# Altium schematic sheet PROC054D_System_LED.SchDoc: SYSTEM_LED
size 558 x 431 mm; Date: Not shown in title block; ApprovedBy: Not shown in title block; CheckedBy: Not shown in title block; Author: Not shown in title block; CompanyName: Not shown in title block; DrawnBy: a0271760; Engineer: Not shown in title block; Organization: Not shown in title block; Address1: Not shown in title block; Address2: Not shown in title block; Address3: Not shown in title block; Address4: Not shown in title block; DocumentNumber: 17; Revision: Use project pAWRameter SCH_Rev; SheetNumber: 17; SheetTotal: 19; PageSetup: Record=PageOptions¦CenterHorizontal=True¦CenterVertical=True¦PrintScale=1.00¦XCorrection=1.00¦YCorrection=1.00¦PrintKind=0¦BorderSize=5000000¦LeftOffset=0¦BottomOffset=0¦Orientation=2¦PaperLength=1000¦PaperWidth=1000¦Scale=100¦PaperSource=15¦PrintQuality=600¦MediaType=1¦DitherType=10¦PaperKind=Letter¦PrintScaleMode=1
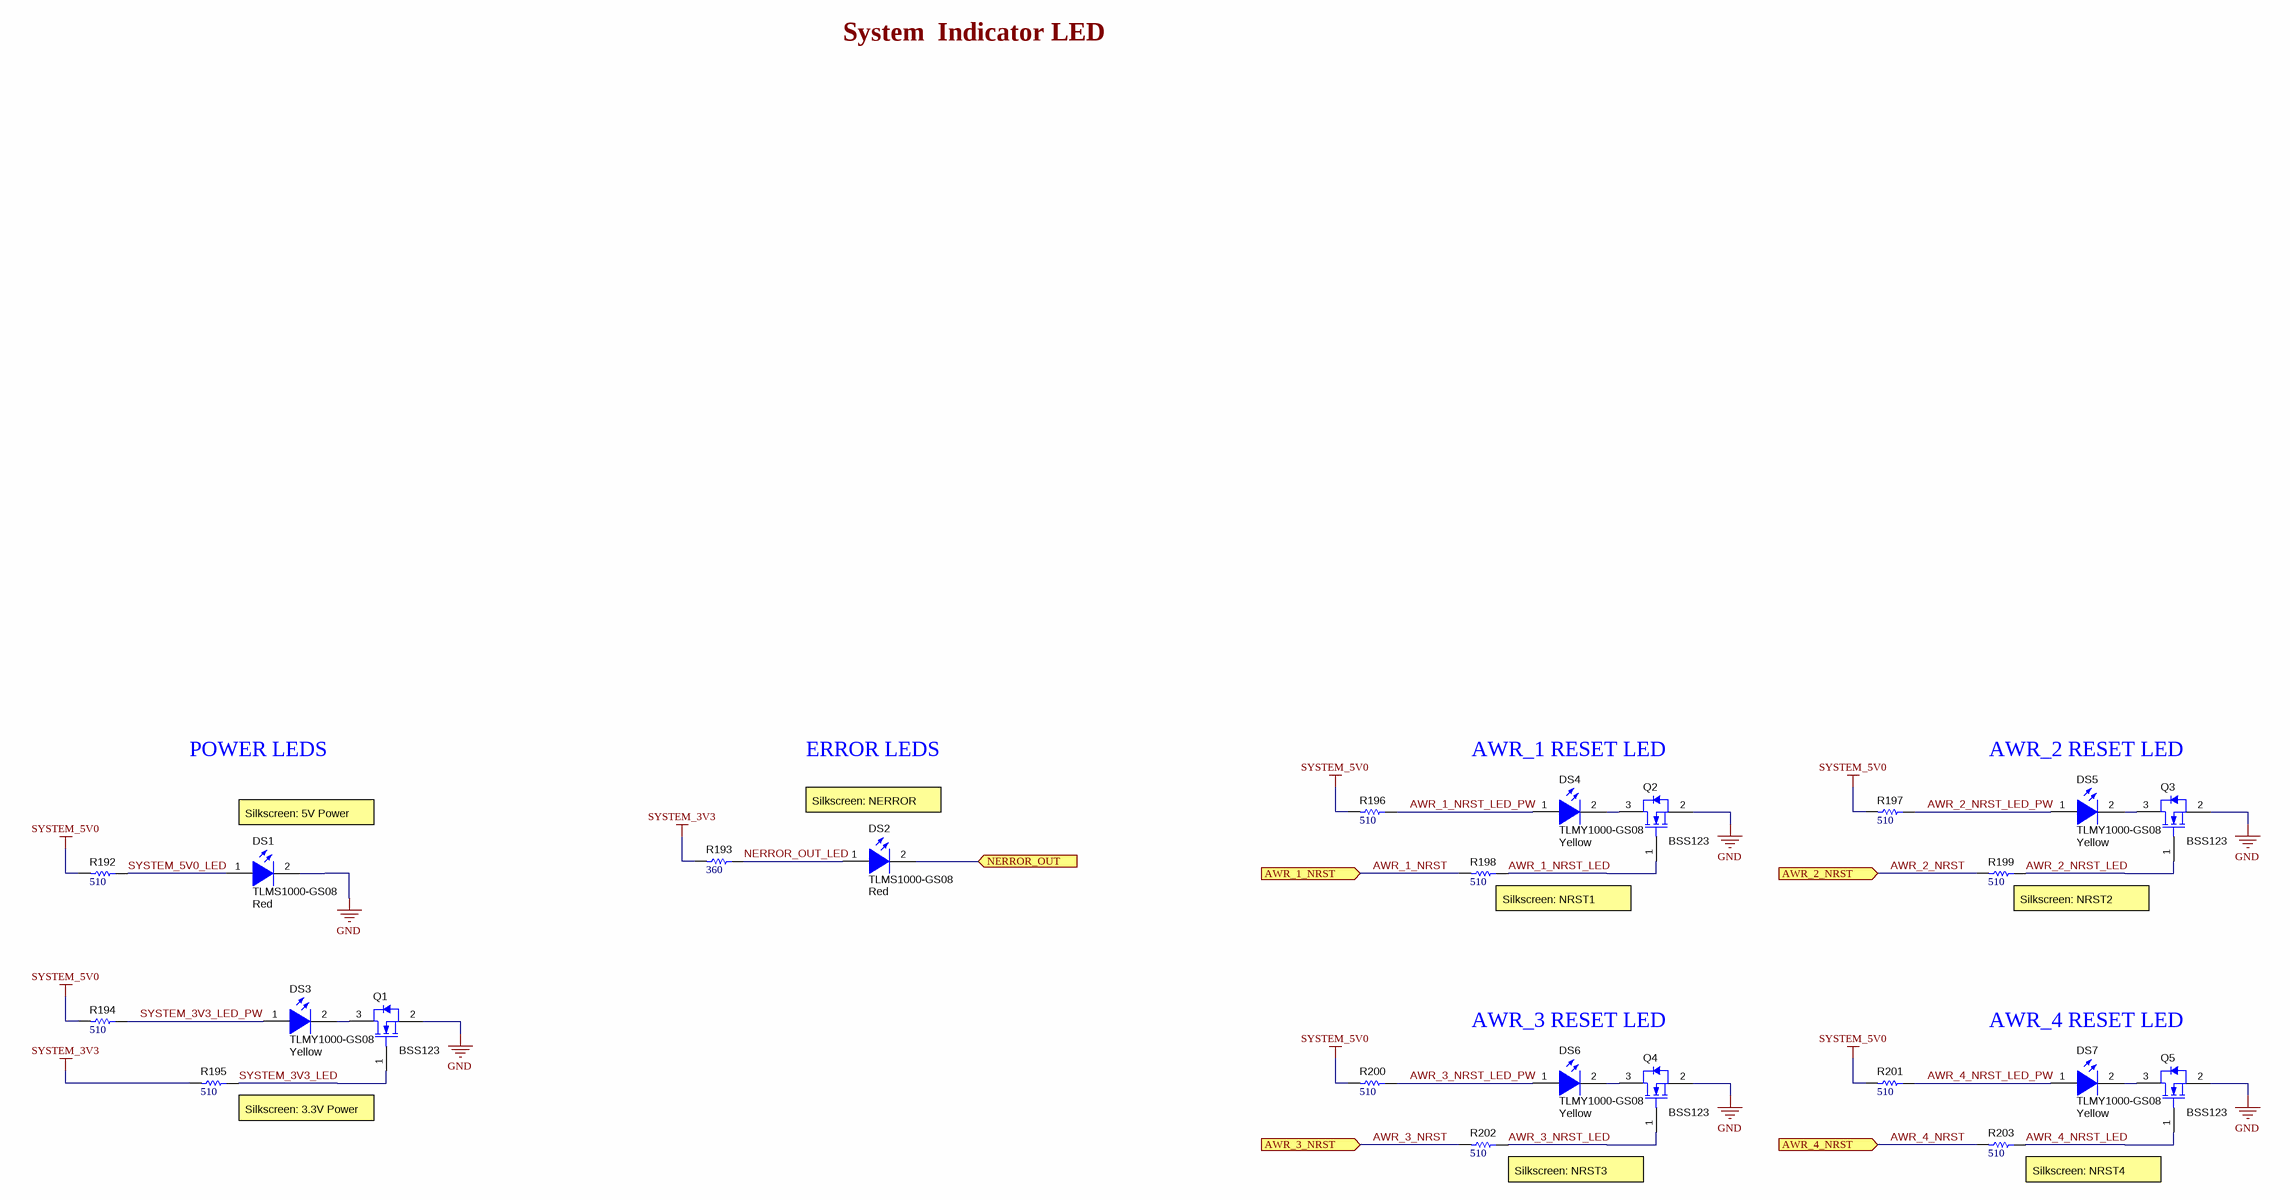
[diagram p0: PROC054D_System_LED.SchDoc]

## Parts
DS1  TLMS1000-GS08  value Red  [TLMx1000_Red]
DS2  TLMS1000-GS08  value Red  [TLMx1000_Red]
DS3  TLMY1000-GS08  value Yellow  [TLMx1000_Yellow]
DS4  TLMY1000-GS08  value Yellow  [TLMx1000_Yellow]
DS5  TLMY1000-GS08  value Yellow  [TLMx1000_Yellow]
DS6  TLMY1000-GS08  value Yellow  [TLMx1000_Yellow]
DS7  TLMY1000-GS08  value Yellow  [TLMx1000_Yellow]
Q1  BSS123  [SOT-23]
Q2  BSS123  [SOT-23]
Q3  BSS123  [SOT-23]
Q4  BSS123  [SOT-23]
Q5  BSS123  [SOT-23]
R192  ValueDisplayed: 510  [0402]  (hidden comment: ERJ-2GEJ511X)
R193  ValueDisplayed: 360  [0402]  (hidden comment: ERJ-2GEJ361X)
R194  ValueDisplayed: 510  [0402]  (hidden comment: ERJ-2GEJ511X)
R195  ValueDisplayed: 510  [0402]  (hidden comment: ERJ-2GEJ511X)
R196  ValueDisplayed: 510  [0402]  (hidden comment: ERJ-2GEJ511X)
R197  ValueDisplayed: 510  [0402]  (hidden comment: ERJ-2GEJ511X)
R198  ValueDisplayed: 510  [0402]  (hidden comment: ERJ-2GEJ511X)
R199  ValueDisplayed: 510  [0402]  (hidden comment: ERJ-2GEJ511X)
R200  ValueDisplayed: 510  [0402]  (hidden comment: ERJ-2GEJ511X)
R201  ValueDisplayed: 510  [0402]  (hidden comment: ERJ-2GEJ511X)
R202  ValueDisplayed: 510  [0402]  (hidden comment: ERJ-2GEJ511X)
R203  ValueDisplayed: 510  [0402]  (hidden comment: ERJ-2GEJ511X)

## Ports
AWR_1_NRST (in), AWR_2_NRST (in), AWR_3_NRST (in), AWR_4_NRST (in), NERROR_OUT (in)

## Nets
GND: DS1.2(K) Q1.2(S) Q2.2(S) Q3.2(S) Q4.2(S) Q5.2(S)
SYSTEM_3V3: R193.2 R195.2
SYSTEM_5V0: R192.2 R194.2 R196.2 R197.2 R200.2 R201.2
AWR_1_NRST: R198.2 ; port AWR_1_NRST
AWR_1_NRST_LED: Q2.1(G) R198.1
AWR_1_NRST_LED_PW: DS4.1(A) R196.1
AWR_2_NRST: R199.2 ; port AWR_2_NRST
AWR_2_NRST_LED: Q3.1(G) R199.1
AWR_2_NRST_LED_PW: DS5.1(A) R197.1
AWR_3_NRST: R202.2 ; port AWR_3_NRST
AWR_3_NRST_LED: Q4.1(G) R202.1
AWR_3_NRST_LED_PW: DS6.1(A) R200.1
AWR_4_NRST: R203.2 ; port AWR_4_NRST
AWR_4_NRST_LED: Q5.1(G) R203.1
AWR_4_NRST_LED_PW: DS7.1(A) R201.1
NERROR_OUT: DS2.2(K) ; port NERROR_OUT
NERROR_OUT_LED: DS2.1(A) R193.1
SYSTEM_3V3_LED: Q1.1(G) R195.1
SYSTEM_3V3_LED_PW: DS3.1(A) R194.1
SYSTEM_5V0_LED: DS1.1(A) R192.1
NetDS3_2: DS3.2(K) Q1.3(D)
NetDS4_2: DS4.2(K) Q2.3(D)
NetDS5_2: DS5.2(K) Q3.3(D)
NetDS6_2: DS6.2(K) Q4.3(D)
NetDS7_2: DS7.2(K) Q5.3(D)

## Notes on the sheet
- System  Indicator LED
- POWER LEDS
- ERROR LEDS
- AWR_1 RESET LED
- AWR_2 RESET LED
- Silkscreen: 5V Power
- Silkscreen: NERROR
- (near R198) Silkscreen: NRST1
- (near R199) Silkscreen: NRST2
- AWR_3 RESET LED
- AWR_4 RESET LED
- (near R195) Silkscreen: 3.3V Power
- (near R202) Silkscreen: NRST3
- (near R203) Silkscreen: NRST4

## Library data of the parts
DS1 DS2 = CMP-0078197-1: LED, Red, SMD; Manufacturer: Vishay-Semiconductor; Tjmax_C: 120°C; SizeAreaWB_mm2: 4.68; Vr_V: 6V; Power_TotalModule: 40mW; Angle: 160; SizeArea_mm2: 1.28; Ir_A: 10µA; SizeZ_mm: 0.65; Io_A: 2mA; Vf_V: 1.8V; SizeY_mm: 0.8; U/M: EA; Value1: .04W; SizeX_mm: 1.6; Type: AlInGaP
DS3-DS7 = CMP-0078196-1: LED, Yellow, SMD; Manufacturer: Vishay-Semiconductor; Tjmax_C: 120°C; SizeAreaWB_mm2: 4.68; Vr_V: 6V; Power_TotalModule: 40mW; Angle: 160; SizeArea_mm2: 1.28; Ir_A: 10µA; SizeZ_mm: 0.65; Io_A: 2mA; Vf_V: 1.8V; SizeY_mm: 0.8; U/M: EA; Value1: .04W; SizeX_mm: 1.6; Type: AlInGaP
Q1-Q5 = CMP-0000947-2: MOSFET, N-CH, 100 V, 0.17 A, SOT-23; Alternate Manufacturer: None; Manufacturer: Fairchild Semiconductor; SizeZ_mm: 1.1; ChType: N; Value2: 1.8 nC; Value1: 1; VdsMax_V: 100V; SizeX_mm: 2.5; SizeY_mm: 3; Vgs_V: 20V; Value: 100V; Rdson45_ohm: 10; SizeArea_mm2: 7.5; AEC Category: Q101; IdsMax_A: 1.7dA; SizeAreaWB_mm2: 14; U/M: EA; QgTyp_nC: 1.8
R192 R194-R203 = CMP-0078212-1: RES, 510, 5%, 0.1 W, AEC-Q200 Grade 0, 0402; Manufacturer: Panasonic; Value_Code: 510R; SizeArea_mm2: 0.5; AEC Qualified: Y; AEC Category: Q200; Value: 510; SizeZ_mm: 0.6; EIA_Code: E24; TempCo: 200 ppm/C; AEC Grade: 0; Power_W: 100mW; VDC_V: 50V; Value2: 0.1W; U/M: EA; SizeX_mm: 1
R193 = CMP-0078194-1: RES, 360, 5%, 0.1 W, AEC-Q200 Grade 0, 0402; Manufacturer: Panasonic; Value_Code: 360R; SizeArea_mm2: 0.5; AEC Qualified: Y; AEC Category: Q200; Value: 360; SizeZ_mm: 0.6; EIA_Code: E24; TempCo: 200 ppm/C; AEC Grade: 0; Power_W: 100mW; VDC_V: 50V; Value2: 0.1W; U/M: EA; SizeX_mm: 1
